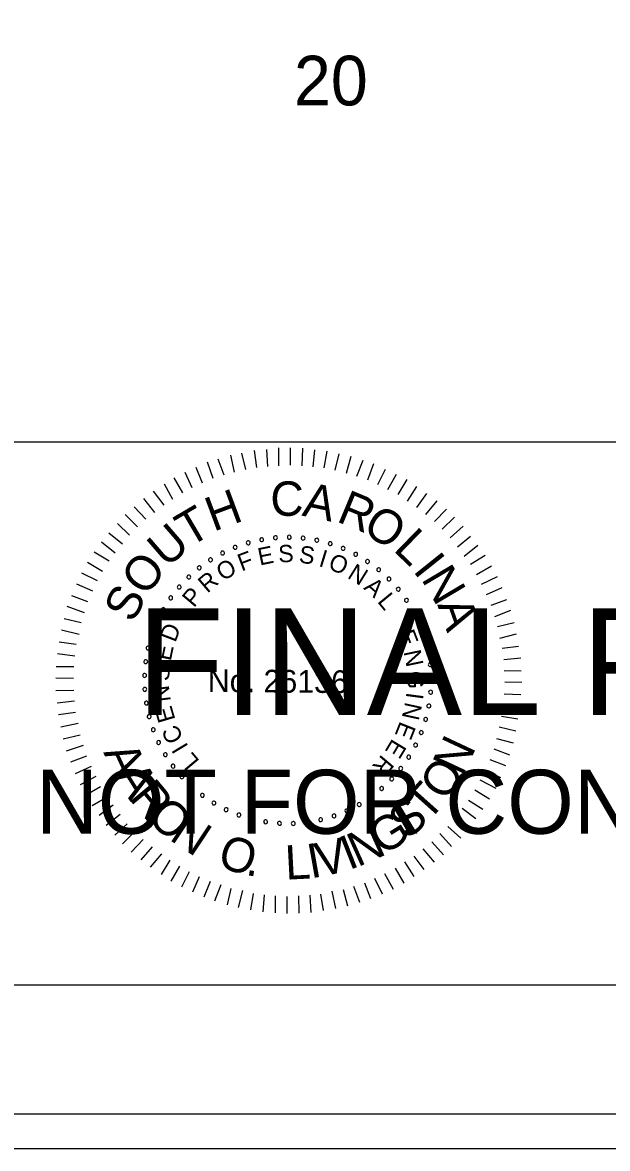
# Model space of a CAD drawing. Extents: x 967 to 1326, y 964 to 3144.
# Drawn here: x 1170.47 to 1189.3, y 963.72 to 1000 of the extents above; entities that cross this region are included whole.
import ezdxf

# ---------------------------------------------------------------- set-up
doc = ezdxf.new("R2010")
doc.units = 0
for name, color, linetype in [('RD_SHT_Bndy', 7, 'Continuous'), ('RD_SHT_IplotShp', 7, 'Continuous'), ('RD_SHT_Misc1', 7, 'Continuous'), ('RD_SHT_Misc2', 7, 'Continuous'), ('RD_SHT_TX', 7, 'Continuous'), ('RD_Sketch1', 7, 'Continuous')]:
    doc.layers.add(name, color=color, linetype=linetype)

msp = doc.modelspace()

# ---------------------------------------------------------------- linework, layer by layer
at = {"layer": 'RD_SHT_Bndy'}
for p, q in [((996.114, 986.486), (1323.886, 986.486)), ((1323.886, 968.983), (996.114, 968.983))]:
    msp.add_line(p, q, dxfattribs=at)
at = {"layer": 'RD_SHT_IplotShp'}
for points in [[(967.409, 963.72), (1326.285, 963.72), (1326.285, 1183.72), (967.409, 1183.72)], [(988.525, 964.84), (1326.285, 964.84), (1326.285, 1182.6), (988.525, 1182.6)]]:
    msp.add_lwpolyline(points, close=True, dxfattribs=at)
at = {"layer": 'RD_SHT_Misc1'}
for p, q in [((1177.657, 985.597), (1177.53, 986.128)), ((1178.01, 985.663), (1177.93, 986.209)), ((1178.364, 985.699), (1178.33, 986.244)), ((1178.717, 985.719), (1178.722, 986.295)), ((1179.093, 985.739), (1179.098, 986.292)), ((1179.469, 985.713), (1179.489, 986.288)), ((1179.829, 985.687), (1179.872, 986.231)), ((1180.174, 985.646), (1180.271, 986.19)), ((1180.535, 985.573), (1180.662, 986.102)), ((1176.61, 985.306), (1176.423, 985.83)), ((1176.964, 985.419), (1176.769, 985.935)), ((1177.287, 985.508), (1177.169, 986.054)), ((1180.902, 985.478), (1181.045, 986.022)), ((1181.231, 985.384), (1181.428, 985.896)), ((1181.584, 985.265), (1181.78, 985.786)), ((1175.933, 985.005), (1175.699, 985.506)), ((1176.264, 985.156), (1176.053, 985.657)), ((1181.905, 985.109), (1182.154, 985.606)), ((1182.226, 984.953), (1182.506, 985.45)), ((1175.308, 984.634), (1175.036, 985.12)), ((1175.624, 984.846), (1175.352, 985.332)), ((1182.562, 984.789), (1182.85, 985.27)), ((1182.86, 984.572), (1183.163, 985.053)), ((1174.729, 984.217), (1174.372, 984.665)), ((1175.03, 984.445), (1174.681, 984.9)), ((1183.158, 984.378), (1183.484, 984.828)), ((1174.435, 983.997), (1174.062, 984.399)), ((1183.447, 984.145), (1183.811, 984.587)), ((1183.729, 983.92), (1184.116, 984.316)), ((1174.172, 983.753), (1173.776, 984.148)), ((1183.98, 983.672), (1184.368, 984.061)), ((1173.684, 983.197), (1173.242, 983.546)), ((1173.909, 983.479), (1173.52, 983.858)), ((1184.232, 983.394), (1184.657, 983.767)), ((1173.451, 982.9), (1173.009, 983.256)), ((1184.475, 983.108), (1184.892, 983.45)), ((1173.257, 982.64), (1172.776, 982.936)), ((1184.687, 982.807), (1185.128, 983.156)), ((1184.885, 982.544), (1185.355, 982.832)), ((1173.039, 982.312), (1172.559, 982.6)), ((1185.081, 982.213), (1185.56, 982.493)), ((1172.883, 982.006), (1172.379, 982.256)), ((1185.24, 981.904), (1185.756, 982.145)), ((1172.727, 981.677), (1172.215, 981.904)), ((1185.399, 981.573), (1185.907, 981.791)), ((1172.571, 981.333), (1172.051, 981.53)), ((1185.549, 981.226), (1186.057, 981.414)), ((1172.461, 980.974), (1171.91, 981.178)), ((1185.669, 980.865), (1186.185, 981.06)), ((1172.351, 980.652), (1171.807, 980.787)), ((1185.759, 980.541), (1186.297, 980.667)), ((1172.286, 980.276), (1171.727, 980.419)), ((1185.832, 980.165), (1186.371, 980.298)), ((1172.191, 979.955), (1171.647, 980.029)), ((1185.906, 979.842), (1186.436, 979.906)), ((1172.15, 979.587), (1171.598, 979.653)), ((1172.124, 979.234), (1171.548, 979.239)), ((1185.964, 979.473), (1186.51, 979.53)), ((1172.105, 978.866), (1171.545, 978.871)), ((1185.977, 979.12), (1186.514, 979.115)), ((1172.118, 978.482), (1171.542, 978.471)), ((1185.997, 978.751), (1186.542, 978.747)), ((1172.138, 978.136), (1171.585, 978.072)), ((1185.971, 978.368), (1186.508, 978.348)), ((1172.173, 977.768), (1171.627, 977.688)), ((1185.952, 978.022), (1186.497, 977.949)), ((1172.262, 977.414), (1171.701, 977.296)), ((1185.888, 977.655), (1186.417, 977.566)), ((1172.321, 977.037), (1171.774, 976.911)), ((1185.808, 977.302), (1186.345, 977.175)), ((1172.425, 976.707), (1171.871, 976.519)), ((1185.729, 976.926), (1186.265, 976.792)), ((1172.53, 976.36), (1172.007, 976.173)), ((1185.634, 976.597), (1186.146, 976.401)), ((1172.681, 976.029), (1172.165, 975.788)), ((1185.352, 975.924), (1185.857, 975.675)), ((1185.508, 976.253), (1186.013, 976.057)), ((1172.831, 975.705), (1172.323, 975.441)), ((1185.188, 975.603), (1185.7, 975.33)), ((1172.982, 975.374), (1172.497, 975.094)), ((1185.024, 975.274), (1185.498, 974.987)), ((1173.194, 975.042), (1172.709, 974.762)), ((1184.822, 974.946), (1185.288, 974.658)), ((1173.384, 974.78), (1172.936, 974.453)), ((1173.612, 974.478), (1173.164, 974.129)), ((1184.62, 974.687), (1185.055, 974.353)), ((1173.832, 974.177), (1173.437, 973.812)), ((1184.155, 974.092), (1184.574, 973.72)), ((1184.403, 974.389), (1184.814, 974.033)), ((1174.091, 973.945), (1173.689, 973.541)), ((1183.899, 973.864), (1184.28, 973.454)), ((1174.35, 973.674), (1173.97, 973.263)), ((1174.64, 973.442), (1174.275, 973.022)), ((1183.358, 973.37), (1183.715, 972.944)), ((1183.644, 973.597), (1184.024, 973.18)), ((1174.937, 973.209), (1174.58, 972.782)), ((1175.212, 973.014), (1174.932, 972.549)), ((1183.065, 973.141), (1183.384, 972.709)), ((1175.525, 972.812), (1175.245, 972.331)), ((1182.463, 972.755), (1182.743, 972.269)), ((1182.764, 972.952), (1183.059, 972.482)), ((1175.83, 972.633), (1175.588, 972.136)), ((1176.159, 972.477), (1175.94, 971.98)), ((1176.503, 972.321), (1176.307, 971.816)), ((1181.476, 972.28), (1181.664, 971.771)), ((1181.8, 972.431), (1182.041, 971.93)), ((1182.124, 972.581), (1182.396, 972.08)), ((1176.855, 972.211), (1176.651, 971.69)), ((1177.177, 972.1), (1177.05, 971.572)), ((1177.545, 972.036), (1177.409, 971.484)), ((1177.897, 971.933), (1177.808, 971.412)), ((1180.061, 971.915), (1180.149, 971.393)), ((1180.423, 972.012), (1180.541, 971.458)), ((1180.791, 972.07), (1180.926, 971.54)), ((1181.122, 972.175), (1181.31, 971.652)), ((1178.25, 971.892), (1178.207, 971.34)), ((1178.603, 971.866), (1178.598, 971.313)), ((1178.978, 971.84), (1178.974, 971.295)), ((1179.355, 971.86), (1179.365, 971.307)), ((1179.715, 971.88), (1179.749, 971.327))]:
    msp.add_line(p, q, dxfattribs=at)
for centre, start, end in [((1177.734, 983.235), 16.1422, 196.1422), ((1177.734, 983.235), 196.1422, 16.1422), ((1178.168, 983.337), 10.6038, 190.6038), ((1178.168, 983.337), 190.6038, 10.6038), ((1178.609, 983.397), 5.0653, 185.0653), ((1178.609, 983.397), 185.0653, 5.0653), ((1179.055, 983.414), 359.5268, 179.5268), ((1179.055, 983.414), 179.5268, 359.5268), ((1179.5, 983.388), 353.9884, 173.9884), ((1179.5, 983.388), 173.9884, 353.9884), ((1179.94, 983.319), 168.4499, 348.4499), ((1179.94, 983.319), 348.4499, 168.4499), ((1180.372, 983.208), 162.9114, 342.9114), ((1180.372, 983.208), 342.9114, 162.9114), ((1176.906, 982.908), 27.2191, 207.2191), ((1176.906, 982.908), 207.2191, 27.2191), ((1177.312, 983.091), 21.6807, 201.6807), ((1177.312, 983.091), 201.6807, 21.6807), ((1180.79, 983.056), 157.373, 337.373), ((1180.79, 983.056), 337.373, 157.373), ((1181.193, 982.864), 151.8345, 331.8345), ((1181.193, 982.864), 331.8345, 151.8345), ((1176.156, 982.428), 38.2961, 218.2961), ((1176.156, 982.428), 218.2961, 38.2961), ((1176.52, 982.686), 32.7576, 212.7576), ((1176.52, 982.686), 212.7576, 32.7576), ((1181.574, 982.634), 146.2961, 326.2961), ((1181.574, 982.634), 326.2961, 146.2961), ((1175.82, 982.135), 43.8345, 223.8345), ((1175.82, 982.135), 223.8345, 43.8345), ((1181.932, 982.368), 140.7576, 320.7576), ((1181.932, 982.368), 320.7576, 140.7576), ((1182.263, 982.069), 135.2191, 315.2191), ((1182.263, 982.069), 315.2191, 135.2191), ((1175.513, 981.812), 49.373, 229.373), ((1175.513, 981.812), 229.373, 49.373), ((1182.563, 981.74), 129.6807, 309.6807), ((1182.563, 981.74), 309.6807, 129.6807), ((1175.239, 981.461), 54.9114, 234.9114), ((1175.239, 981.461), 234.9114, 54.9114), ((1182.83, 981.383), 124.1422, 304.1422), ((1182.83, 981.383), 304.1422, 124.1422), ((1175, 981.085), 60.4499, 240.4499), ((1175, 981.085), 240.4499, 60.4499), ((1183.061, 981.002), 118.6038, 298.6038), ((1183.061, 981.002), 298.6038, 118.6038), ((1174.798, 980.687), 65.9884, 245.9884), ((1174.798, 980.687), 245.9884, 65.9884), ((1183.255, 980.601), 113.0653, 293.0653), ((1183.255, 980.601), 293.0653, 113.0653), ((1174.636, 980.272), 71.5268, 251.5268), ((1174.636, 980.272), 251.5268, 71.5268), ((1174.514, 979.843), 77.0653, 257.0653), ((1174.514, 979.843), 257.0653, 77.0653), ((1183.408, 980.182), 107.5268, 287.5268), ((1183.408, 980.182), 287.5268, 107.5268), ((1183.521, 979.751), 101.9884, 281.9884), ((1183.521, 979.751), 281.9884, 101.9884), ((1174.435, 979.405), 82.6038, 262.6038), ((1174.435, 979.405), 262.6038, 82.6038), ((1183.592, 979.311), 96.4499, 276.4499), ((1183.592, 979.311), 276.4499, 96.4499), ((1174.398, 978.961), 88.1422, 268.1422), ((1174.398, 978.961), 268.1422, 88.1422), ((1183.619, 978.866), 90.9114, 270.9114), ((1183.619, 978.866), 270.9114, 90.9114), ((1174.404, 978.515), 93.6807, 273.6807), ((1174.404, 978.515), 273.6807, 93.6807), ((1183.604, 978.421), 85.373, 265.373), ((1183.604, 978.421), 265.373, 85.373), ((1174.453, 978.072), 99.2191, 279.2191), ((1174.453, 978.072), 279.2191, 99.2191), ((1183.546, 977.979), 79.8345, 259.8345), ((1183.546, 977.979), 259.8345, 79.8345), ((1174.545, 977.636), 104.7576, 284.7576), ((1174.545, 977.636), 284.7576, 104.7576), ((1183.445, 977.545), 74.2961, 254.2961), ((1183.445, 977.545), 254.2961, 74.2961), ((1174.678, 977.211), 110.2961, 290.2961), ((1174.678, 977.211), 290.2961, 110.2961), ((1183.303, 977.122), 68.7576, 248.7576), ((1183.303, 977.122), 248.7576, 68.7576), ((1174.852, 976.8), 115.8345, 295.8345), ((1174.852, 976.8), 295.8345, 115.8345), ((1183.121, 976.716), 63.2191, 243.2191), ((1183.121, 976.716), 243.2191, 63.2191), ((1175.065, 976.409), 121.373, 301.373), ((1175.065, 976.409), 301.373, 121.373), ((1182.9, 976.328), 57.6807, 237.6807), ((1182.9, 976.328), 237.6807, 57.6807), ((1175.314, 976.039), 126.9114, 306.9114), ((1175.314, 976.039), 306.9114, 126.9114), ((1182.643, 975.964), 52.1422, 232.1422), ((1182.643, 975.964), 232.1422, 52.1422), ((1175.598, 975.696), 132.4499, 312.4499), ((1175.598, 975.696), 312.4499, 132.4499), ((1182.353, 975.627), 46.6038, 226.6038), ((1182.353, 975.627), 226.6038, 46.6038), ((1175.914, 975.381), 137.9884, 317.9884), ((1175.914, 975.381), 317.9884, 137.9884), ((1182.03, 975.319), 41.0653, 221.0653), ((1182.03, 975.319), 221.0653, 41.0653), ((1176.258, 975.099), 143.5268, 323.5268), ((1176.258, 975.099), 323.5268, 143.5268), ((1176.629, 974.851), 149.0653, 329.0653), ((1176.629, 974.851), 329.0653, 149.0653), ((1181.305, 974.803), 29.9884, 209.9884), ((1181.305, 974.803), 209.9884, 29.9884), ((1181.68, 975.043), 35.5268, 215.5268), ((1181.68, 975.043), 215.5268, 35.5268), ((1177.021, 974.639), 154.6038, 334.6038), ((1177.021, 974.639), 334.6038, 154.6038), ((1177.432, 974.467), 160.1422, 340.1422), ((1177.432, 974.467), 340.1422, 160.1422), ((1180.494, 974.436), 18.9114, 198.9114), ((1180.494, 974.436), 198.9114, 18.9114), ((1180.908, 974.6), 24.4499, 204.4499), ((1180.908, 974.6), 204.4499, 24.4499), ((1177.858, 974.335), 165.6807, 345.6807), ((1177.858, 974.335), 345.6807, 165.6807), ((1178.294, 974.245), 351.2191, 171.2191), ((1178.294, 974.245), 171.2191, 351.2191), ((1178.737, 974.198), 356.7576, 176.7576), ((1178.737, 974.198), 176.7576, 356.7576), ((1179.183, 974.193), 2.2961, 182.2961), ((1179.183, 974.193), 182.2961, 2.2961), ((1179.627, 974.232), 7.8345, 187.8345), ((1179.627, 974.232), 187.8345, 7.8345), ((1180.065, 974.313), 13.373, 193.373), ((1180.065, 974.313), 193.373, 13.373)]:
    msp.add_arc(centre, 0.0627, start, end, dxfattribs=at)
at = {"layer": 'RD_Sketch1'}
msp.add_lwpolyline([(967.409, 963.72), (1326.285, 963.72), (1326.285, 1183.72), (967.409, 1183.72)], close=True, dxfattribs=at)

# ---------------------------------------------------------------- texts
at = {"layer": 'RD_SHT_Misc1'}
for s, height, rotation, p in [('C', 1.11, 359.5482, (1178.442, 984.108)), ('A', 1.11, 348.1981, (1179.439, 984.115)), ('H', 1.11, 20.3637, (1176.614, 983.587)), ('R', 1.11, 337.4344, (1180.541, 983.937)), ('T', 1.11, 30.4992, (1175.828, 983.072)), ('O', 1.108, 326.5869, (1181.366, 983.609)), ('U', 1.11, 40.8022, (1175.102, 982.403)), ('L', 1.11, 315.9488, (1182.373, 983.003)), ('S', 0.557, 2.208, (1178.709, 982.601)), ('O', 1.11, 52.0267, (1174.435, 981.474)), ('F', 0.557, 20.6127, (1177.52, 982.309)), ('E', 0.557, 11.4103, (1178.103, 982.503)), ('S', 0.557, 352.6608, (1179.346, 982.599)), ('I', 0.557, 343.1136, (1179.975, 982.491)), ('O', 0.557, 338.4392, (1180.274, 982.401)), ('I', 1.11, 308.6613, (1183.011, 982.338)), ('O', 0.557, 30.8477, (1176.917, 981.987)), ('N', 0.557, 328.2042, (1180.896, 982.12)), ('N', 1.11, 300.7037, (1183.285, 982.075)), ('R', 0.557, 40.3949, (1176.415, 981.594)), ('S', 1.108, 63.2511, (1174.029, 980.619)), ('P', 0.557, 49.9421, (1175.985, 981.124)), ('A', 0.557, 318.657, (1181.424, 981.762)), ('L', 0.557, 309.4546, (1181.869, 981.339)), ('A', 1.11, 289.4792, (1183.814, 981.243)), ('D', 0.557, 69.0364, (1175.386, 980.003)), ('E', 0.557, 291.049, (1182.53, 980.307)), ('E', 0.557, 78.2388, (1175.238, 979.407)), ('N', 0.557, 281.8466, (1182.728, 979.726)), ('S', 0.557, 87.786, (1175.187, 978.772)), ('No. 26136', 0.7311, 359.5268, (1176.429, 978.43)), ('G', 0.557, 272.2995, (1182.833, 979.097)), ('N', 0.557, 97.3332, (1175.242, 978.137)), ('I', 0.557, 262.4084, (1182.83, 978.437)), ('E', 0.557, 106.5355, (1175.394, 977.541)), ('N', 0.557, 257.7339, (1182.789, 978.127)), ('E', 0.557, 248.1867, (1182.628, 977.511)), ('C', 0.557, 116.4266, (1175.661, 976.938)), ('N', 1.105, 64.8922, (1184.632, 975.684)), ('I', 0.557, 121.1011, (1175.823, 976.67)), ('E', 0.557, 238.9844, (1182.378, 976.949)), ('A', 1.105, 294.7297, (1173.062, 976.486)), ('L', 0.557, 129.9595, (1176.187, 976.204)), ('R', 0.557, 229.782, (1182.041, 976.435)), ('A', 1.105, 302.2892, (1173.414, 975.72)), ('O', 1.105, 56.2059, (1184.102, 974.874)), ('R', 1.105, 309.8487, (1173.865, 975.007)), ('T', 1.105, 48.2685, (1183.515, 974.211)), ('O', 1.105, 317.7861, (1174.434, 974.33)), ('S', 1.105, 40.3311, (1182.842, 973.636)), ('N', 1.105, 326.4725, (1175.158, 973.686)), ('G', 1.105, 32.0198, (1182.059, 973.14)), ('N', 1.105, 24.0824, (1181.252, 972.776)), ('O', 1.105, 342.3472, (1176.697, 972.82)), ('V', 1.105, 12.7741, (1180.033, 972.457)), ('I', 1.105, 21.4605, (1180.976, 972.681)), ('L', 1.105, 2.9677, (1178.943, 972.379)), ('I', 1.105, 10.1523, (1179.743, 972.418)), ('.', 1.105, 351.0336, (1177.623, 972.536))]:
    msp.add_text(s, height=height, rotation=rotation, dxfattribs=at).set_placement(p)
at = {"layer": 'RD_SHT_Misc2'}
for s, height, p in [('FINAL PLANS', 3.4375, (1174.145, 977.685)), ('NOT FOR CONSTRUCTION', 2.0625, (1170.901, 973.86))]:
    msp.add_text(s, height=height, dxfattribs=at).set_placement(p)
at = {"layer": 'RD_SHT_TX'}
msp.add_text('20', height=1.6, dxfattribs=at).set_placement((1179.203, 997.329))

doc.saveas('drawing.dxf')
